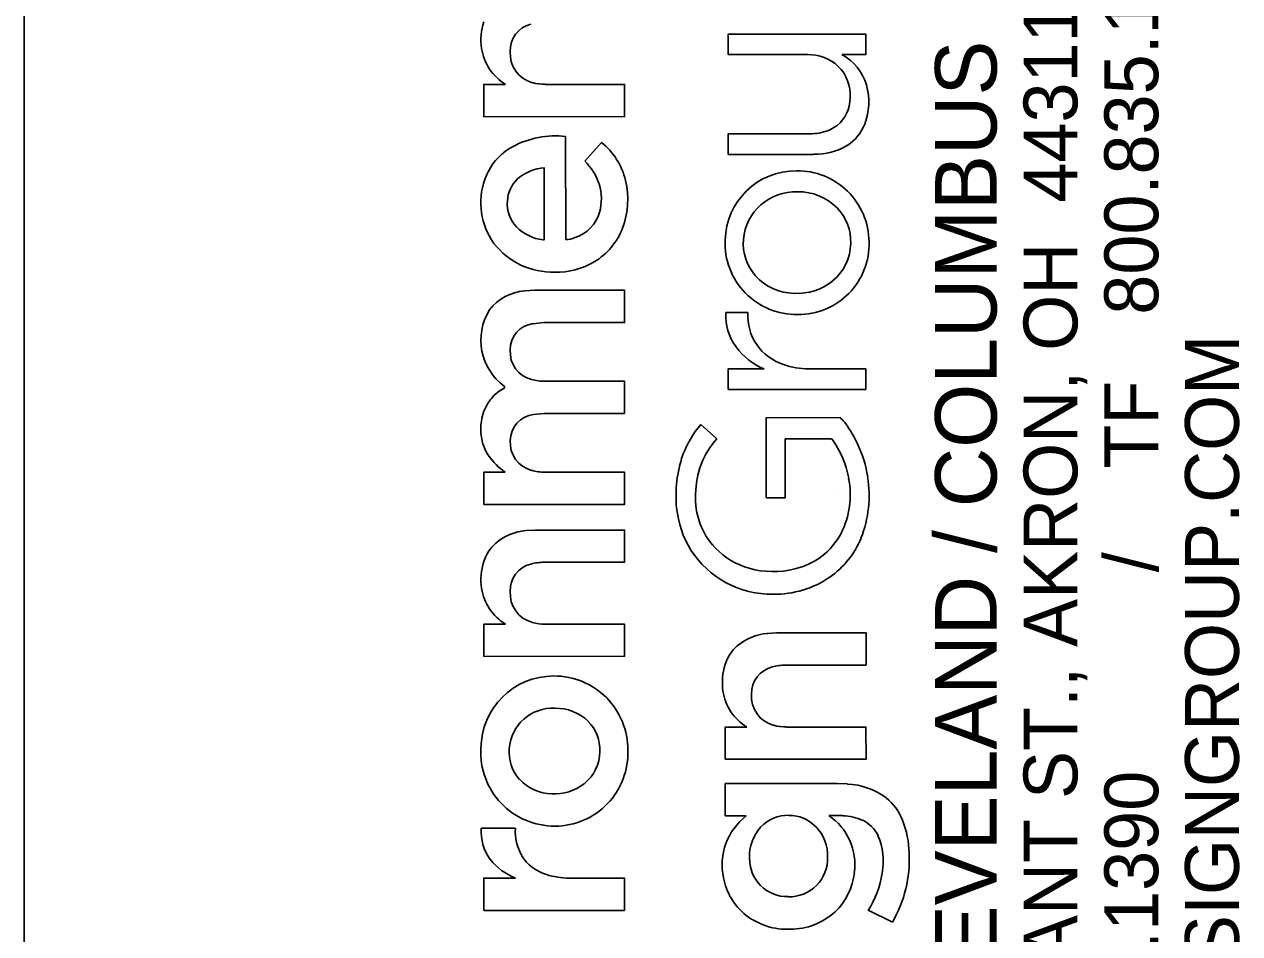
# Model space of a CAD drawing. Extents: x -0.3 to 34, y 0 to 22.
# Drawn here: x 32 to 33.125, y 3.094 to 3.936 of the extents above; entities that cross this region are included whole.
import ezdxf

# ---------------------------------------------------------------- set-up
doc = ezdxf.new("R2010")
doc.units = 0
doc.layers.add('RD_X_Misc_Items', color=7, linetype='Continuous')
doc.layers.add('SV_X_Control_Cells_Found', color=7, linetype='Continuous')

msp = doc.modelspace()

# ---------------------------------------------------------------- linework, layer by layer
at = {"layer": 'RD_X_Misc_Items'}
for p, q in [((32.6515, 3.908), (32.6515, 3.9267)), ((32.6515, 3.9267), (32.7791, 3.9266)), ((32.7791, 3.9266), (32.7791, 3.908)), ((32.7249, 3.908), (32.6515, 3.908)), ((32.7328, 3.9073), (32.7249, 3.908)), ((32.7791, 3.908), (32.7569, 3.908)), ((32.4254, 3.8503), (32.4254, 3.8802)), ((32.4254, 3.8802), (32.4455, 3.8802)), ((32.4822, 3.8802), (32.5557, 3.8802)), ((32.5557, 3.8802), (32.5557, 3.8504)), ((32.5557, 3.8504), (32.4254, 3.8503)), ((32.5011, 3.8321), (32.5012, 3.7366)), ((32.5188, 3.8093), (32.5342, 3.8266)), ((32.6515, 3.8344), (32.7291, 3.8345)), ((32.6517, 3.8154), (32.6515, 3.8344)), ((32.7307, 3.8154), (32.6517, 3.8154)), ((32.4814, 3.7364), (32.4814, 3.803)), ((32.4802, 3.7363), (32.4814, 3.7364)), ((32.4633, 3.6891), (32.4726, 3.6897)), ((32.4726, 3.6897), (32.5556, 3.6897)), ((32.5556, 3.6897), (32.5557, 3.6598)), ((32.6493, 3.6691), (32.6698, 3.6691)), ((32.4806, 3.6598), (32.471, 3.6588)), ((32.5557, 3.6598), (32.4806, 3.6598)), ((32.6515, 3.598), (32.6515, 3.617)), ((32.6515, 3.617), (32.6848, 3.617)), ((32.726, 3.617), (32.7791, 3.617)), ((32.7791, 3.617), (32.779, 3.598)), ((32.4444, 3.5992), (32.4446, 3.6007)), ((32.4822, 3.6055), (32.5557, 3.6055)), ((32.5557, 3.6055), (32.5557, 3.5757)), ((32.779, 3.598), (32.6515, 3.598)), ((32.4809, 3.5757), (32.4714, 3.5747)), ((32.5557, 3.5757), (32.4809, 3.5757)), ((32.6868, 3.5718), (32.7552, 3.5719)), ((32.6868, 3.4978), (32.6868, 3.5718)), ((32.6264, 3.5655), (32.6411, 3.5524)), ((32.7045, 3.5524), (32.7043, 3.4978)), ((32.7474, 3.5523), (32.7045, 3.5524)), ((32.4254, 3.4915), (32.4254, 3.5214)), ((32.4254, 3.5214), (32.4451, 3.5214)), ((32.4821, 3.5214), (32.5557, 3.5214)), ((32.5557, 3.5214), (32.5557, 3.4916)), ((32.75, 3.5), (32.75, 3.5)), ((32.5557, 3.4916), (32.4254, 3.4915)), ((32.7043, 3.4978), (32.6868, 3.4978)), ((32.4644, 3.4674), (32.4729, 3.4678)), ((32.4729, 3.4678), (32.5557, 3.4678)), ((32.5557, 3.4678), (32.5557, 3.438)), ((32.5557, 3.438), (32.4814, 3.438)), ((32.4254, 3.3509), (32.4254, 3.3807)), ((32.4254, 3.3807), (32.4455, 3.3807)), ((32.4822, 3.3807), (32.5557, 3.3807)), ((32.5557, 3.3807), (32.5557, 3.351)), ((32.6878, 3.3722), (32.6963, 3.3727)), ((32.6963, 3.3727), (32.7792, 3.3727)), ((32.7792, 3.3727), (32.7792, 3.3429)), ((32.5557, 3.351), (32.4254, 3.3509)), ((32.7792, 3.3429), (32.7048, 3.3428)), ((32.6489, 3.2557), (32.6489, 3.2855)), ((32.6489, 3.2855), (32.669, 3.2855)), ((32.7057, 3.2855), (32.7791, 3.2855)), ((32.7791, 3.2855), (32.7792, 3.2558)), ((32.7792, 3.2558), (32.6489, 3.2557)), ((32.6489, 3.2034), (32.6489, 3.2332)), ((32.6489, 3.2332), (32.7524, 3.2332)), ((32.7524, 3.2332), (32.7619, 3.2329)), ((32.6684, 3.2034), (32.6489, 3.2034)), ((32.7576, 3.2036), (32.7449, 3.2036)), ((32.423, 3.1919), (32.4545, 3.1919)), ((32.4254, 3.1159), (32.4254, 3.1458)), ((32.4254, 3.1458), (32.4547, 3.1458)), ((32.5041, 3.1458), (32.5557, 3.1457)), ((32.5557, 3.1457), (32.5556, 3.1159)), ((32.5556, 3.1159), (32.4254, 3.1159)), ((32.8036, 3.1049), (32.7812, 3.116))]:
    msp.add_line(p, q, dxfattribs=at)
for points in [[(32.7328, 3.9073), (32.7249, 3.908), (32.6515, 3.908), (32.6515, 3.9267), (32.7791, 3.9266), (32.7791, 3.908), (32.7569, 3.908)], [(32.4254, 3.8503), (32.4254, 3.8802), (32.4455, 3.8802)], [(32.4822, 3.8802), (32.5557, 3.8802), (32.5557, 3.8504), (32.4254, 3.8503)], [(32.5011, 3.8321), (32.5012, 3.7366)], [(32.5188, 3.8093), (32.5342, 3.8266)], [(32.7307, 3.8154), (32.6517, 3.8154), (32.6515, 3.8344), (32.7291, 3.8345)], [(32.4802, 3.7363), (32.4814, 3.7364), (32.4814, 3.803)], [(32.4633, 3.6891), (32.4726, 3.6897), (32.5556, 3.6897), (32.5557, 3.6598), (32.4806, 3.6598), (32.471, 3.6588)], [(32.6493, 3.6691), (32.6698, 3.6691)], [(32.6515, 3.598), (32.6515, 3.617), (32.6848, 3.617)], [(32.726, 3.617), (32.7791, 3.617), (32.779, 3.598), (32.6515, 3.598)], [(32.4444, 3.5992), (32.4446, 3.6007)], [(32.4822, 3.6055), (32.5557, 3.6055), (32.5557, 3.5757), (32.4809, 3.5757), (32.4714, 3.5747)], [(32.7474, 3.5523), (32.7045, 3.5524), (32.7043, 3.4978), (32.6868, 3.4978), (32.6868, 3.5718), (32.7552, 3.5719)], [(32.6264, 3.5655), (32.6411, 3.5524)], [(32.4254, 3.4915), (32.4254, 3.5214), (32.4451, 3.5214)], [(32.4821, 3.5214), (32.5557, 3.5214), (32.5557, 3.4916), (32.4254, 3.4915)], [(32.4644, 3.4674), (32.4729, 3.4678), (32.5557, 3.4678), (32.5557, 3.438), (32.4814, 3.438)], [(32.4254, 3.3509), (32.4254, 3.3807), (32.4455, 3.3807)], [(32.4822, 3.3807), (32.5557, 3.3807), (32.5557, 3.351), (32.4254, 3.3509)], [(32.6878, 3.3722), (32.6963, 3.3727), (32.7792, 3.3727), (32.7792, 3.3429), (32.7048, 3.3428)], [(32.6489, 3.2557), (32.6489, 3.2855), (32.669, 3.2855)], [(32.7057, 3.2855), (32.7791, 3.2855), (32.7792, 3.2558), (32.6489, 3.2557)], [(32.6684, 3.2034), (32.6489, 3.2034), (32.6489, 3.2332), (32.7524, 3.2332), (32.7619, 3.2329)], [(32.7576, 3.2036), (32.7449, 3.2036)], [(32.423, 3.1919), (32.4545, 3.1919)], [(32.4254, 3.1159), (32.4254, 3.1458), (32.4547, 3.1458)], [(32.5041, 3.1458), (32.5557, 3.1457), (32.5556, 3.1159), (32.4254, 3.1159)], [(32.8036, 3.1049), (32.7812, 3.116)]]:
    msp.add_lwpolyline(points, dxfattribs=at)
for centre, radius, start, end in [((32.4787, 3.9211), 0.056, 162.274, 187.7917), ((32.4787, 3.9211), 0.056, 162.274, 187.7917), ((32.4748, 3.9116), 0.025, 103.6868, 182.214), ((32.4748, 3.9116), 0.025, 103.6868, 182.214), ((32.4703, 3.9209), 0.0476, 188.9646, 238.6987), ((32.4703, 3.9209), 0.0476, 188.9646, 238.6987), ((32.4774, 3.9085), 0.0276, 175.5844, 255.1382), ((32.4774, 3.9085), 0.0276, 175.5844, 255.1382), ((32.7271, 3.87), 0.0377, 33.5008, 81.3295), ((32.7271, 3.87), 0.0377, 33.5008, 81.3295), ((32.7324, 3.8648), 0.0496, 17.6221, 60.3897), ((32.7324, 3.8648), 0.0496, 17.6221, 60.3897), ((32.4818, 3.9224), 0.0421, 254.0891, 270.5284), ((32.4818, 3.9224), 0.0421, 254.0891, 270.5284), ((32.7241, 3.8695), 0.0405, 346.5618, 31.7539), ((32.7241, 3.8695), 0.0405, 346.5618, 31.7539), ((32.7234, 3.8641), 0.0584, 339.162, 15.6148), ((32.7234, 3.8641), 0.0584, 339.162, 15.6148), ((32.7337, 3.8662), 0.0304, 294.6321, 348.4863), ((32.7337, 3.8662), 0.0304, 294.6321, 348.4863), ((32.7275, 3.8808), 0.0463, 271.952, 294.0894), ((32.7275, 3.8808), 0.0463, 271.952, 294.0894), ((32.739, 3.859), 0.042, 303.1039, 338.1561), ((32.739, 3.859), 0.042, 303.1039, 338.1561), ((32.4918, 3.7487), 0.0839, 83.6212, 118.2845), ((32.4918, 3.7487), 0.0839, 83.6212, 118.2845), ((32.494, 3.7763), 0.0644, 13.5328, 51.3627), ((32.494, 3.7763), 0.0644, 13.5328, 51.3627), ((32.4789, 3.7737), 0.0558, 118.8294, 160.6224), ((32.4789, 3.7737), 0.0558, 118.8294, 160.6224), ((32.7321, 3.8726), 0.0571, 268.627, 301.4778), ((32.7321, 3.8726), 0.0571, 268.627, 301.4778), ((32.4844, 3.7607), 0.0424, 94.0131, 130.8806), ((32.4844, 3.7607), 0.0424, 94.0131, 130.8806), ((32.4803, 3.7702), 0.0549, 19.0387, 45.4432), ((32.4803, 3.7702), 0.0549, 19.0387, 45.4432), ((32.487, 3.7707), 0.0644, 160.5214, 215.7815), ((32.487, 3.7707), 0.0644, 160.5214, 215.7815), ((32.477, 3.7709), 0.0298, 132.9855, 177.1802), ((32.477, 3.7709), 0.0298, 132.9855, 177.1802), ((32.7143, 3.7348), 0.0655, 89.4821, 178.7775), ((32.7143, 3.7348), 0.0655, 89.4821, 178.7775), ((32.7158, 3.7341), 0.0662, 0.4227, 90.7613), ((32.7158, 3.7341), 0.0662, 0.4227, 90.7613), ((32.4872, 3.7743), 0.047, 344.6072, 17.0067), ((32.4872, 3.7743), 0.047, 344.6072, 17.0067), ((32.4829, 3.7738), 0.0758, 339.3543, 13.3771), ((32.4829, 3.7738), 0.0758, 339.3543, 13.3771), ((32.714, 3.7324), 0.0485, 87.6883, 175.017), ((32.714, 3.7324), 0.0485, 87.6883, 175.017), ((32.7166, 3.7304), 0.0505, 44.912, 90.7591), ((32.7166, 3.7304), 0.0505, 44.912, 90.7591), ((32.4782, 3.7697), 0.0311, 175.0014, 223.2876), ((32.4782, 3.7697), 0.0311, 175.0014, 223.2876), ((32.499, 3.7718), 0.035, 288.0108, 343.5536), ((32.499, 3.7718), 0.035, 288.0108, 343.5536), ((32.7196, 3.7345), 0.0455, 358.3228, 43.8349), ((32.7196, 3.7345), 0.0455, 358.3228, 43.8349), ((32.4855, 3.7783), 0.0423, 225.0645, 262.797), ((32.4855, 3.7783), 0.0423, 225.0645, 262.797), ((32.4955, 3.7698), 0.0626, 300.9439, 338.7322), ((32.4955, 3.7698), 0.0626, 300.9439, 338.7322), ((32.5013, 3.7568), 0.0202, 269.7004, 294.8729), ((32.5013, 3.7568), 0.0202, 269.7004, 294.8729), ((32.7148, 3.7334), 0.0661, 177.5373, 270.9452), ((32.7148, 3.7334), 0.0661, 177.5373, 270.9452), ((32.7108, 3.7331), 0.0453, 175.5147, 221.4205), ((32.7108, 3.7331), 0.0453, 175.5147, 221.4205), ((32.4891, 3.7752), 0.0687, 217.7434, 271.6561), ((32.4891, 3.7752), 0.0687, 217.7434, 271.6561), ((32.7167, 3.7327), 0.0654, 269.3083, 1.6791), ((32.7167, 3.7327), 0.0654, 269.3083, 1.6791), ((32.7193, 3.7337), 0.0457, 308.9038, 359.3095), ((32.7193, 3.7337), 0.0457, 308.9038, 359.3095), ((32.492, 3.777), 0.0706, 269.2053, 300.3357), ((32.492, 3.777), 0.0706, 269.2053, 300.3357), ((32.714, 3.7373), 0.0505, 222.6626, 268.3733), ((32.714, 3.7373), 0.0505, 222.6626, 268.3733), ((32.7157, 3.7386), 0.0518, 266.5531, 308.6725), ((32.7157, 3.7386), 0.0518, 266.5531, 308.6725), ((32.4664, 3.644), 0.0452, 93.9112, 142.3072), ((32.4664, 3.644), 0.0452, 93.9112, 142.3072), ((32.4759, 3.6437), 0.0532, 148.2879, 233.9556), ((32.4759, 3.6437), 0.0532, 148.2879, 233.9556), ((32.6988, 3.6666), 0.0495, 177.1621, 216.2802), ((32.6988, 3.6666), 0.0495, 177.1621, 216.2802), ((32.7173, 3.6664), 0.0476, 176.7699, 252.1504), ((32.7173, 3.6664), 0.0476, 176.7699, 252.1504), ((32.4738, 3.635), 0.024, 96.7576, 181.6251), ((32.4738, 3.635), 0.024, 96.7576, 181.6251), ((32.4758, 3.6324), 0.026, 175.8157, 256.1672), ((32.4758, 3.6324), 0.026, 175.8157, 256.1672), ((32.7098, 3.6755), 0.0637, 216.9153, 246.8862), ((32.7098, 3.6755), 0.0637, 216.9153, 246.8862), ((32.7269, 3.6917), 0.0747, 251.1388, 269.3469), ((32.7269, 3.6917), 0.0747, 251.1388, 269.3469), ((32.4817, 3.6505), 0.045, 254.3463, 270.6103), ((32.4817, 3.6505), 0.045, 254.3463, 270.6103), ((32.4619, 3.5645), 0.0387, 139.5245, 154.847), ((32.4619, 3.5645), 0.0387, 139.5245, 154.847), ((32.4638, 3.5627), 0.0414, 117.9163, 139.243), ((32.4638, 3.5627), 0.0414, 117.9163, 139.243), ((32.4714, 3.5612), 0.0488, 156.0638, 187.3493), ((32.4714, 3.5612), 0.0488, 156.0638, 187.3493), ((32.4742, 3.5506), 0.0243, 96.5532, 179.949), ((32.4742, 3.5506), 0.0243, 96.5532, 179.949), ((32.725, 3.5394), 0.0444, 30.9891, 47.161), ((32.725, 3.5394), 0.0444, 30.9891, 47.161), ((32.7016, 3.5019), 0.0986, 139.7948, 159.137), ((32.7016, 3.5019), 0.0986, 139.7948, 159.137), ((32.6709, 3.5002), 0.1111, 25.3031, 33.9618), ((32.6709, 3.5002), 0.1111, 25.3031, 33.9618), ((32.4646, 3.5597), 0.0418, 186.5579, 213.3885), ((32.4646, 3.5597), 0.0418, 186.5579, 213.3885), ((32.4761, 3.5486), 0.0263, 175.722, 255.7863), ((32.4761, 3.5486), 0.0263, 175.722, 255.7863), ((32.699, 3.5008), 0.0775, 138.258, 179.7006), ((32.699, 3.5008), 0.0775, 138.258, 179.7006), ((32.6789, 3.501), 0.0856, 10.0751, 36.8319), ((32.6789, 3.501), 0.0856, 10.0751, 36.8319), ((32.6704, 3.4999), 0.1117, 8.8034, 25.3348), ((32.6704, 3.4999), 0.1117, 8.8034, 25.3348), ((32.4789, 3.5708), 0.0598, 214.7043, 235.6872), ((32.4789, 3.5708), 0.0598, 214.7043, 235.6872), ((32.7187, 3.4997), 0.1154, 161.1438, 185.6281), ((32.7187, 3.4997), 0.1154, 161.1438, 185.6281), ((32.4819, 3.5652), 0.0438, 253.6672, 270.1498), ((32.4819, 3.5652), 0.0438, 253.6672, 270.1498), ((32.6842, 3.5006), 0.0804, 333.4669, 11.0367), ((32.6842, 3.5006), 0.0804, 333.4669, 11.0367), ((32.6756, 3.4998), 0.1065, 338.2887, 9.2855), ((32.6756, 3.4998), 0.1065, 338.2887, 9.2855), ((32.6881, 3.4973), 0.0668, 176.6658, 223.6912), ((32.6881, 3.4973), 0.0668, 176.6658, 223.6912), ((32.6934, 3.497), 0.0899, 185.5077, 212.0129), ((32.6934, 3.497), 0.0899, 185.5077, 212.0129), ((32.4687, 3.4177), 0.0499, 94.9706, 130.2248), ((32.4687, 3.4177), 0.0499, 94.9706, 130.2248), ((32.4635, 3.426), 0.0402, 132.2238, 161.6823), ((32.4635, 3.426), 0.0402, 132.2238, 161.6823), ((32.6987, 3.4955), 0.0652, 282.8815, 331.8147), ((32.6987, 3.4955), 0.0652, 282.8815, 331.8147), ((32.6984, 3.4917), 0.0824, 305.0306, 337.6757), ((32.6984, 3.4917), 0.0824, 305.0306, 337.6757), ((32.6921, 3.4975), 0.0891, 212.7022, 270.714), ((32.6921, 3.4975), 0.0891, 212.7022, 270.714), ((32.6905, 3.5001), 0.0704, 224.0215, 253.88), ((32.6905, 3.5001), 0.0704, 224.0215, 253.88), ((32.4787, 3.4216), 0.056, 162.274, 187.7917), ((32.4787, 3.4216), 0.056, 162.274, 187.7917), ((32.4748, 3.4121), 0.025, 103.6868, 182.214), ((32.4748, 3.4121), 0.025, 103.6868, 182.214), ((32.4811, 3.392), 0.046, 89.6051, 105.3303), ((32.4811, 3.392), 0.046, 89.6051, 105.3303), ((32.6932, 3.5125), 0.0831, 254.4535, 283.9512), ((32.6932, 3.5125), 0.0831, 254.4535, 283.9512), ((32.6943, 3.4998), 0.0914, 269.3273, 304.1963), ((32.6943, 3.4998), 0.0914, 269.3273, 304.1963), ((32.4703, 3.4214), 0.0476, 188.9646, 238.6987), ((32.4703, 3.4214), 0.0476, 188.9646, 238.6987), ((32.4774, 3.409), 0.0276, 175.5844, 255.1382), ((32.4774, 3.409), 0.0276, 175.5844, 255.1382), ((32.4818, 3.4229), 0.0421, 254.0891, 270.5284), ((32.4818, 3.4229), 0.0421, 254.0891, 270.5284), ((32.6922, 3.3225), 0.0499, 94.9706, 130.2248), ((32.6922, 3.3225), 0.0499, 94.9706, 130.2248), ((32.6869, 3.3309), 0.0402, 132.2238, 161.6823), ((32.6869, 3.3309), 0.0402, 132.2238, 161.6823), ((32.7022, 3.3264), 0.056, 162.274, 187.7917), ((32.7022, 3.3264), 0.056, 162.274, 187.7917), ((32.7045, 3.2968), 0.046, 89.6051, 105.3303), ((32.7045, 3.2968), 0.046, 89.6051, 105.3303), ((32.4901, 3.2654), 0.0674, 89.8476, 179.6405), ((32.4901, 3.2654), 0.0674, 89.8476, 179.6405), ((32.4906, 3.2647), 0.0681, 359.5401, 90.2114), ((32.4906, 3.2647), 0.0681, 359.5401, 90.2114), ((32.6983, 3.3169), 0.025, 103.6868, 182.214), ((32.6983, 3.3169), 0.025, 103.6868, 182.214), ((32.6937, 3.3262), 0.0476, 188.9646, 238.6987), ((32.6937, 3.3262), 0.0476, 188.9646, 238.6987), ((32.7008, 3.3138), 0.0276, 175.5844, 255.1382), ((32.7008, 3.3138), 0.0276, 175.5844, 255.1382), ((32.4892, 3.2626), 0.0404, 87.0481, 175.5726), ((32.4892, 3.2626), 0.0404, 87.0481, 175.5726), ((32.492, 3.26), 0.043, 45.8426, 90.9801), ((32.492, 3.26), 0.043, 45.8426, 90.9801), ((32.4946, 3.2642), 0.0382, 357.8857, 44.159), ((32.4946, 3.2642), 0.0382, 357.8857, 44.159), ((32.7053, 3.3277), 0.0421, 254.0891, 270.5284), ((32.7053, 3.3277), 0.0421, 254.0891, 270.5284), ((32.4908, 3.2621), 0.0682, 176.8344, 270.4038), ((32.4908, 3.2621), 0.0682, 176.8344, 270.4038), ((32.4873, 3.2625), 0.0385, 175.1538, 221.1471), ((32.4873, 3.2625), 0.0385, 175.1538, 221.1471), ((32.4912, 3.2614), 0.0675, 270.0624, 2.3776), ((32.4912, 3.2614), 0.0675, 270.0624, 2.3776), ((32.4945, 3.2632), 0.0383, 308.2894, 359.4347), ((32.4945, 3.2632), 0.0383, 308.2894, 359.4347), ((32.4892, 3.2661), 0.0423, 223.0999, 268.8089), ((32.4892, 3.2661), 0.0423, 223.0999, 268.8089), ((32.491, 3.2679), 0.0442, 266.5651, 308.0608), ((32.491, 3.2679), 0.0442, 266.5651, 308.0608), ((32.7591, 3.1679), 0.065, 53.4034, 87.4906), ((32.7591, 3.1679), 0.065, 53.4034, 87.4906), ((32.7652, 3.1804), 0.0514, 21.6075, 50.5577), ((32.7652, 3.1804), 0.0514, 21.6075, 50.5577), ((32.7029, 3.1581), 0.0569, 127.3748, 192.2247), ((32.7029, 3.1581), 0.0569, 127.3748, 192.2247), ((32.7069, 3.1693), 0.0346, 88.473, 136.4256), ((32.7069, 3.1693), 0.0346, 88.473, 136.4256), ((32.7081, 3.1696), 0.0342, 44.2719, 90.4762), ((32.7081, 3.1696), 0.0342, 44.2719, 90.4762), ((32.7142, 3.1583), 0.0547, 352.1125, 55.923), ((32.7142, 3.1583), 0.0547, 352.1125, 55.923), ((32.7567, 3.1572), 0.0463, 65.0169, 88.8011), ((32.7567, 3.1572), 0.0463, 65.0169, 88.8011), ((32.7626, 3.1716), 0.0309, 26.2681, 63.803), ((32.7626, 3.1716), 0.0309, 26.2681, 63.803), ((32.7307, 3.1671), 0.0884, 1.1514, 21.3627), ((32.7307, 3.1671), 0.0884, 1.1514, 21.3627), ((32.4662, 3.1888), 0.0433, 175.8731, 216.3475), ((32.4662, 3.1888), 0.0433, 175.8731, 216.3475), ((32.5009, 3.1895), 0.0464, 176.9688, 209.6064), ((32.5009, 3.1895), 0.0464, 176.9688, 209.6064), ((32.7114, 3.166), 0.0401, 137.4674, 182.3324), ((32.7114, 3.166), 0.0401, 137.4674, 182.3324), ((32.7037, 3.166), 0.04, 358.5714, 43.5376), ((32.7037, 3.166), 0.04, 358.5714, 43.5376), ((32.7357, 3.1615), 0.0595, 349.3073, 23.4307), ((32.7357, 3.1615), 0.0595, 349.3073, 23.4307), ((32.4747, 3.1972), 0.0551, 218.0981, 248.7907), ((32.4747, 3.1972), 0.0551, 218.0981, 248.7907), ((32.4951, 3.1881), 0.0408, 211.9447, 253.2028), ((32.4951, 3.1881), 0.0408, 211.9447, 253.2028), ((32.7065, 3.1637), 0.0351, 178.8821, 271.0837), ((32.7065, 3.1637), 0.0351, 178.8821, 271.0837), ((32.7082, 3.164), 0.0355, 268.2788, 1.5502), ((32.7082, 3.164), 0.0355, 268.2788, 1.5502), ((32.7054, 3.1624), 0.1138, 329.6388, 3.26), ((32.7054, 3.1624), 0.1138, 329.6388, 3.26), ((32.7099, 3.1571), 0.0589, 313.742, 353.8554), ((32.7099, 3.1571), 0.0589, 313.742, 353.8554), ((32.7074, 3.1633), 0.0877, 327.3149, 351.5748), ((32.7074, 3.1633), 0.0877, 327.3149, 351.5748), ((32.5047, 3.2165), 0.0707, 252.4655, 269.573), ((32.5047, 3.2165), 0.0707, 252.4655, 269.573), ((32.7046, 3.157), 0.0584, 190.7518, 231.2892), ((32.7046, 3.157), 0.0584, 190.7518, 231.2892), ((32.7063, 3.1611), 0.0627, 232.4606, 272.5902), ((32.7063, 3.1611), 0.0627, 232.4606, 272.5902), ((32.7095, 3.159), 0.0605, 269.6361, 312.7088), ((32.7095, 3.159), 0.0605, 269.6361, 312.7088)]:
    msp.add_arc(centre, radius, start, end, dxfattribs=at)
at = {"layer": 'SV_X_Control_Cells_Found'}
msp.add_line((32, 0.5), (32, 21.5), dxfattribs=at)

# ---------------------------------------------------------------- texts
at = {"layer": 'RD_X_Misc_Items'}
for s, height, p in [('800.835.1390', 0.049846, (33.0497, 3.6671)), ('450 GRANT ST., AKRON, OH  44311', 0.049846, (32.9749, 2.8374)), ('AKRON / CLEVELAND / COLUMBUS', 0.056969, (32.9001, 2.638)), ('ENVDESIGNGROUP.COM', 0.049846, (33.1244, 2.8374)), ('TF', 0.04985, (33.0497, 3.5246)), ('/  ', 0.04985, (33.0497, 3.4288)), ('330.375.1390', 0.049846, (33.0497, 2.8374))]:
    msp.add_text(s, height=height, rotation=90, dxfattribs=at).set_placement(p)

doc.saveas('drawing.dxf')
